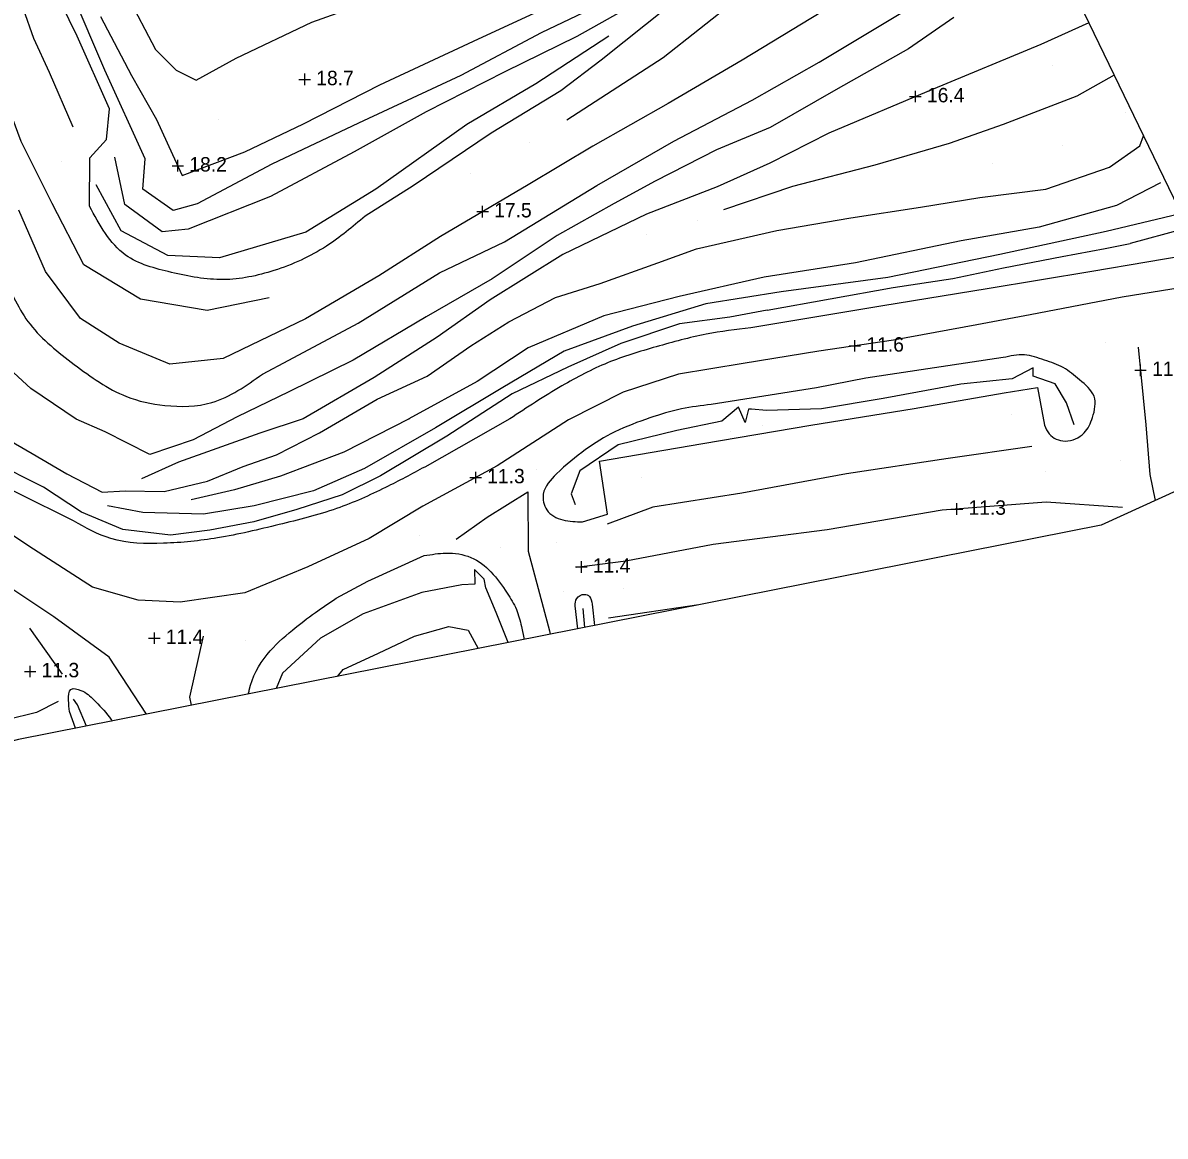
# Model space of a CAD drawing. Extents: x 2316231 to 2323598, y 363169 to 371906.
# Drawn here: x 2320484 to 2320880.2, y 369532.1 to 369918.1 of the extents above; entities that cross this region are included whole.
import ezdxf

# ---------------------------------------------------------------- set-up
doc = ezdxf.new("R2010")
doc.units = 0
for name, color, linetype in [('RD_DTM_BkLn1', 7, 'Continuous'), ('RD_DTM_Holes', 7, 'Continuous'), ('RD_DTM_Spot', 7, 'Continuous'), ('RD_DTM_TinHull', 7, 'Continuous'), ('RD_DTM_Void', 7, 'Continuous'), ('RD_EX_H2O', 7, 'Continuous'), ('RD_EX_Road', 7, 'Continuous')]:
    doc.layers.add(name, color=color, linetype=linetype)

msp = doc.modelspace()

# ---------------------------------------------------------------- linework, layer by layer
at = {"layer": 'RD_DTM_BkLn1'}
for p, q in [((2320678.249, 369715.097), (2320678.781, 369708.485)), ((2320718.471, 369716.35), (2320687.203, 369711.715)), ((2320497.804, 369692.273), (2320486.438, 369708.269))]:
    msp.add_line(p, q, dxfattribs=at)
for points in [[(2320890.624, 370119.716), (2320854.67, 370105.096), (2320824.737, 370091.718), (2320798.041, 370073.658), (2320761.256, 370054.377), (2320722.698, 370033.486), (2320697.589, 370022.782), (2320670.573, 370008.164), (2320638.057, 369990.65), (2320598.275, 369970.046), (2320568.854, 369953.416), (2320537.164, 369939.293), (2320520.212, 369927.706), (2320530.002, 369908.919), (2320537.229, 369901.735), (2320544.104, 369898.284), (2320558.001, 369905.94), (2320584.209, 369918.359), (2320607.024, 369926.567), (2320672.197, 369958.233), (2320716.019, 369979.773), (2320778.692, 370010.373), (2320825.216, 370034.958), (2320852.125, 370018.044)], [(2320879.005, 370020.78), (2320867.89, 370014.415), (2320857.257, 370007.846), (2320852.965, 369994.208), (2320826.144, 369975.823), (2320796.908, 369960.249), (2320762.152, 369944.511), (2320731.25, 369925.921), (2320706.051, 369906.01), (2320672.683, 369884.375)], [(2320846.121, 370003.875), (2320819.758, 369989.692), (2320786.161, 369974.117), (2320753.683, 369959.773), (2320725.332, 369945.903), (2320695.859, 369930.004), (2320663.758, 369914.691), (2320635.931, 369899.875), (2320600.474, 369883.297), (2320570.391, 369869.121), (2320544.447, 369855.352), (2320536.196, 369853.087), (2320525.687, 369860.434), (2320526.469, 369871.019), (2320512.487, 369901.765), (2320501.093, 369928.271), (2320493.497, 369945.114)], [(2320569.459, 369822.765), (2320547.933, 369818.395), (2320524.884, 369822.284), (2320505.191, 369834.205), (2320494.254, 369855.46), (2320483.409, 369876.949), (2320477.252, 369893.898), (2320466.119, 369909.363), (2320454.644, 369921.515), (2320476.509, 369937.799), (2320484.205, 369923.024), (2320487.742, 369912.811), (2320493.16, 369901.06), (2320501.409, 369882.112)], [(2320719.422, 369937.163), (2320697.207, 369925.152), (2320676.162, 369913.406), (2320651.158, 369901.105), (2320623.864, 369887.23), (2320598.965, 369873.389), (2320569.932, 369857.915), (2320541.38, 369846.609), (2320532.372, 369845.664), (2320519.389, 369855.192), (2320515.983, 369871.61)], [(2320761.155, 369921.965), (2320733.465, 369905.215), (2320707.874, 369890.151), (2320681.734, 369875.372), (2320659.231, 369861.923), (2320628.86, 369844.084), (2320607.503, 369830.462), (2320582.025, 369815.476), (2320553.529, 369801.787), (2320535.061, 369799.763), (2320517.402, 369807.066), (2320503.988, 369815.607), (2320491.892, 369831.92), (2320482.631, 369853.166)], [(2320806.943, 369919.979), (2320791.175, 369909.106), (2320766.76, 369895.42), (2320743.267, 369881.864), (2320724.614, 369874.141), (2320703.281, 369863.239), (2320689.113, 369855.517), (2320669.387, 369844.416), (2320646.753, 369829.417), (2320623.858, 369816.207), (2320598.638, 369801.198), (2320576.237, 369790.144), (2320558.388, 369781.496), (2320543.163, 369773.509), (2320528.041, 369768.512), (2320512.532, 369776.31), (2320502.503, 369780.676), (2320486.817, 369791.352), (2320474.931, 369802.246)], [(2320853.737, 369918.105), (2320837.036, 369910.626), (2320799.718, 369895.181), (2320763.548, 369879.832), (2320743.151, 369869.499), (2320724.799, 369861.314), (2320700.359, 369851.776), (2320671.278, 369837.865), (2320646.111, 369822.114), (2320627.68, 369809.174), (2320605.882, 369795.216), (2320581.205, 369780.846), (2320566.197, 369775.882), (2320538.033, 369765.834), (2320525.223, 369759.983)], [(2320687.269, 369913.532), (2320661.986, 369896.994), (2320638.064, 369882.89), (2320606.446, 369860.515), (2320582.215, 369845.501), (2320552.225, 369836.62), (2320534.288, 369837.482), (2320518.097, 369846.036), (2320509.495, 369861.951)], [(2320862.477, 369900.047), (2320849.618, 369892.725), (2320824.064, 369882.889), (2320805.349, 369876.347), (2320779.513, 369868.749), (2320750.969, 369861.378), (2320727.065, 369853.344)], [(2320461.89, 369783.469), (2320487.259, 369768.766), (2320499.343, 369761.794), (2320511.531, 369755.372), (2320519.537, 369755.806), (2320533.094, 369755.673), (2320548.04, 369759.198), (2320560.475, 369764.252), (2320572.006, 369768.322), (2320586.926, 369775.928), (2320606.891, 369787.646), (2320624.264, 369795.611), (2320639.423, 369806.127), (2320652.639, 369814.494), (2320668.755, 369822.903), (2320684.202, 369827.786), (2320704.291, 369834.94), (2320717.635, 369839.787), (2320745.533, 369846.105), (2320771.174, 369850.545), (2320795.305, 369854.228), (2320815.972, 369857.613), (2320838.828, 369860.447), (2320860.876, 369868.086), (2320871.433, 369875.499), (2320872.696, 369878.933)], [(2320878.622, 369862.672), (2320863.318, 369854.843), (2320836.538, 369847.295), (2320809.491, 369842.513), (2320772.852, 369834.956), (2320741.093, 369829.916), (2320711.676, 369823.258), (2320685.552, 369816.549), (2320659.329, 369805.457), (2320641.612, 369793.728), (2320617.942, 369780.803), (2320617.965, 369780.814), (2320595.414, 369769.221), (2320573.364, 369760.908), (2320557.456, 369756.151), (2320542.432, 369752.682)], [(2320886.875, 369854.365), (2320887.419, 369852.354), (2320859.79, 369845.8), (2320822.868, 369837.839), (2320784.046, 369829.81), (2320747.027, 369824.896), (2320720.871, 369820.74), (2320695.484, 369812.994), (2320671.745, 369804.329), (2320650.55, 369791.718), (2320627.167, 369777.678), (2320602.537, 369763.622), (2320584.839, 369755.805), (2320564.208, 369750.61), (2320546.635, 369747.749), (2320525.628, 369748.402), (2320513.364, 369750.676)], [(2320899.096, 369828.432), (2320865.244, 369823.009), (2320833.334, 369816.902), (2320814.869, 369813.372), (2320785.942, 369808.06), (2320760.046, 369804.318), (2320733.9, 369800.015), (2320711.478, 369796.268), (2320692.18, 369790.032), (2320673.259, 369780.434), (2320648.519, 369764.523), (2320622.809, 369750.54), (2320604.151, 369739.366), (2320582.823, 369729.464), (2320561.039, 369720.532), (2320538.574, 369717.201), (2320524.064, 369717.923), (2320508.146, 369722.418), (2320486.114, 369736.621), (2320466.942, 369749.551)], [(2320742.207, 369818.546), (2320729.212, 369816.124), (2320711.776, 369813.713), (2320691.464, 369806.932), (2320673, 369798.759), (2320653.709, 369789.465), (2320631.099, 369774.792), (2320608.044, 369761.043), (2320594.815, 369754.464), (2320579.064, 369749.414), (2320564.091, 369745.068), (2320548.89, 369742.174), (2320535.303, 369740.542), (2320518.686, 369742.444), (2320504.427, 369748.493), (2320491.204, 369757.123), (2320473.183, 369766.125)], [(2320870.882, 369805.693), (2320873.495, 369778.768), (2320874.929, 369761.517), (2320876.694, 369752.51)], [(2320848.662, 369778.765), (2320845.956, 369786.354), (2320842.031, 369792.961), (2320834.456, 369795.572), (2320834.402, 369798.472), (2320827.122, 369794.641), (2320809.385, 369792.838), (2320782.405, 369787.91), (2320761.017, 369784.326), (2320741.904, 369783.688), (2320736.769, 369784.185), (2320735.645, 369784.235), (2320734.487, 369779.564), (2320732.231, 369784.926), (2320726.407, 369780.031), (2320710.788, 369776.824), (2320690.54, 369771.773), (2320677.198, 369762.766), (2320674.17, 369754.81), (2320675.624, 369751.094)], [(2320526.896, 369678.387), (2320513.953, 369698.153), (2320494.831, 369712.151), (2320473.9, 369726.057), (2320453.263, 369740.557), (2320436.136, 369753.107), (2320412.476, 369763.057), (2320387.554, 369770.125), (2320361.478, 369773.264), (2320347.912, 369773.734)], [(2320833.989, 369771.203), (2320804.989, 369767.116), (2320769.71, 369761.767), (2320733.424, 369755.029), (2320702.543, 369750.244), (2320686.709, 369744.273)], [(2320634.265, 369739.13), (2320645.026, 369746.689), (2320659.121, 369755.479), (2320659.269, 369734.951), (2320666.7, 369707.34), (2320666.891, 369706.129)], [(2320865.442, 369750.13), (2320838.955, 369751.888), (2320802.868, 369749.174), (2320762.95, 369742.341), (2320723.412, 369737.305), (2320693.145, 369731.505), (2320676.058, 369729.249)], [(2320496.24, 369682.771), (2320488.769, 369678.962), (2320478.493, 369676.404), (2320476.678, 369691.645), (2320469.359, 369710.049), (2320458.349, 369727.582), (2320445.265, 369739.427)], [(2320652.309, 369703.239), (2320648.183, 369713.669), (2320644.548, 369722.185), (2320643.978, 369725.279), (2320640.644, 369728.589), (2320640.822, 369723.507), (2320636.246, 369723.304), (2320622.372, 369720.628), (2320602.091, 369713.195), (2320587.323, 369704.745), (2320574.101, 369692.657), (2320571.875, 369687.3)], [(2320593.209, 369691.528), (2320595.073, 369693.916), (2320607.387, 369699.545), (2320619.893, 369705.442), (2320631.747, 369708.836), (2320638.474, 369707.533), (2320641.995, 369701.195)], [(2320542.526, 369681.485), (2320541.978, 369684.258), (2320546.701, 369705.515)], [(2320506.167, 369674.28), (2320503.025, 369681.625), (2320501.641, 369683.666)]]:
    msp.add_lwpolyline(points, dxfattribs=at)
at = {"layer": 'RD_DTM_Holes'}
msp.add_lwpolyline([(2321124.606, 370283.08), (2321175.43, 370167.171), (2321165.892, 370142.913), (2321102.435, 370077.997), (2320995.795, 370021.474), (2320962.442, 369979.593), (2320898.768, 369979.08), (2320851.962, 369921.773), (2320884.841, 369853.84), (2320943.763, 369869.068), (2321020.605, 369919.215), (2321168.221, 369992.199), (2321311.04, 369921.856), (2321333.631, 369793.28), (2321191.287, 369743.45), (2321181.751, 369712.515), (2321194.283, 369686.43), (2321363.394, 369755.241)], dxfattribs=at)
at = {"layer": 'RD_DTM_Spot'}
for p, q in [((2320841.104, 369903.401), (2320841.104, 369903.401)), ((2320581.797, 369898.529), (2320581.797, 369898.529)), ((2320866.588, 369887.113), (2320866.588, 369887.113)), ((2320551.76, 369884.533), (2320551.76, 369884.533)), ((2320659.673, 369876.558), (2320659.673, 369876.558)), ((2320844.656, 369875.449), (2320844.656, 369875.449)), ((2320497.303, 369869.935), (2320497.303, 369869.935)), ((2320639.117, 369865.888), (2320639.117, 369865.888)), ((2320820.334, 369869.406), (2320820.334, 369869.406)), ((2320717.929, 369849.431), (2320717.929, 369849.431)), ((2320700.213, 369844.852), (2320700.213, 369844.852)), ((2320859.491, 369807.4), (2320859.491, 369807.4)), ((2320826.781, 369782.299), (2320826.781, 369782.299)), ((2320740.62, 369778.467), (2320740.62, 369778.467)), ((2320729.447, 369776.362), (2320729.447, 369776.362)), ((2320662.239, 369763.299), (2320662.239, 369763.299)), ((2320838.669, 369762.659), (2320838.669, 369762.659)), ((2320864.61, 369766.344), (2320864.61, 369766.344)), ((2320698.512, 369760.347), (2320698.512, 369760.347)), ((2320621.535, 369740.305), (2320621.535, 369740.305)), ((2320649.798, 369736.267), (2320649.798, 369736.267)), ((2320668.996, 369737.951), (2320668.996, 369737.951)), ((2320671.712, 369720.884), (2320671.712, 369720.884)), ((2320692.255, 369721.909), (2320692.255, 369721.909)), ((2320529.655, 369704.766), (2320529.655, 369704.766)), ((2320561.105, 369703.973), (2320561.105, 369703.973)), ((2320486.556, 369693.205), (2320486.556, 369693.205))]:
    msp.add_line(p, q, dxfattribs=at)
at = {"layer": 'RD_DTM_TinHull'}
msp.add_lwpolyline([(2321400.963, 368599.408), (2321534.916, 368777.939), (2321271.463, 369044.178), (2321175.279, 369261.496), (2321099.267, 369551.406), (2321096.219, 369852.637), (2320858.06, 369744.011), (2320482.587, 369669.607), (2320232.924, 369604.892), (2319951.333, 369602.051), (2320092.085, 369259.27), (2319866.523, 369058.699), (2319771.694, 369171.639), (2319557.442, 369523.873), (2318254.179, 368711.432)], dxfattribs=at)
at = {"layer": 'RD_DTM_Void'}
for p, q in [((2320579.797, 369898.529), (2320583.797, 369898.529)), ((2320581.797, 369896.529), (2320581.797, 369900.529)), ((2320793.587, 369890.579), (2320793.587, 369894.579)), ((2320791.587, 369892.579), (2320795.587, 369892.579)), ((2320537.771, 369866.586), (2320537.771, 369870.586)), ((2320535.771, 369868.586), (2320539.771, 369868.586)), ((2320643.493, 369850.679), (2320643.493, 369854.679)), ((2320641.493, 369852.679), (2320645.493, 369852.679)), ((2320770.585, 369806.13), (2320774.585, 369806.13)), ((2320772.585, 369804.13), (2320772.585, 369808.13)), ((2320871.66, 369795.677), (2320871.66, 369799.677)), ((2320869.66, 369797.677), (2320873.66, 369797.677)), ((2320641.08, 369758.477), (2320641.08, 369762.477)), ((2320639.08, 369760.477), (2320643.08, 369760.477)), ((2320807.99, 369747.559), (2320807.99, 369751.559)), ((2320805.99, 369749.559), (2320809.99, 369749.559)), ((2320677.742, 369727.472), (2320677.742, 369731.472)), ((2320675.742, 369729.472), (2320679.742, 369729.472)), ((2320527.655, 369704.766), (2320531.655, 369704.766)), ((2320529.655, 369702.766), (2320529.655, 369706.766)), ((2320486.556, 369691.205), (2320486.556, 369695.205)), ((2320484.556, 369693.205), (2320488.556, 369693.205))]:
    msp.add_line(p, q, dxfattribs=at)
at = {"layer": 'RD_EX_H2O'}
for points in [[(2320942.446, 369852.459), (2320923.822, 369850.683), (2320901.566, 369848.812), (2320886.019, 369846.493), (2320868.021, 369841.679)], [(2320742.207, 369818.546), (2320785.862, 369826.372), (2320806.584, 369829.487), (2320824.15, 369833.202), (2320844.538, 369837.128), (2320859.401, 369839.843), (2320868.021, 369841.679)]]:
    msp.add_lwpolyline(points, dxfattribs=at)
at = {"layer": 'RD_EX_Road'}
for p, q in [((2320824.066, 369802.052), (2320776.357, 369794.987)), ((2320652.925, 369780.802), (2320623.426, 369764.116)), ((2320676.502, 369708.033), (2320675.544, 369715.942)), ((2320681.438, 369716.554), (2320682.332, 369709.189)), ((2320656.973, 369708.815), (2320657.894, 369704.346)), ((2320502.313, 369673.516), (2320500.181, 369679.323))]:
    msp.add_line(p, q, dxfattribs=at)
for points in [[(2320567.105, 369796.337), (2320576.268, 369801.205), (2320600.386, 369813.982), (2320628.552, 369831.473), (2320651.132, 369842.245), (2320683.14, 369861.684), (2320709.778, 369877.068), (2320736.973, 369891.371), (2320760.171, 369904.501), (2320780.972, 369916.968), (2320800.68, 369928.912), (2320833.766, 369947.986), (2320858.279, 369963.381), (2320874.221, 369975.388), (2320892.051, 369982.519), (2320906.767, 369982.695), (2320925.078, 369982.494), (2320949.188, 369984.176), (2320964.962, 369996.308), (2320974.51, 370008.706), (2320986.355, 370021.913), (2320992.021, 370026.256)], [(2320841.864, 370009.258), (2320847.28, 370011.109), (2320851.506, 370008.615), (2320850.576, 370002.347), (2320840.724, 369994.47), (2320805.963, 369977.663), (2320766.893, 369960.136), (2320747.805, 369950.785), (2320730.157, 369939.506), (2320707.97, 369923.819), (2320684.632, 369905.147), (2320670.586, 369894.615), (2320646.458, 369879.926), (2320619.379, 369861.622), (2320602.713, 369851.068)], [(2320507.133, 369854.577), (2320507.259, 369871.371), (2320513.034, 369877.728), (2320514.041, 369888.346), (2320502.899, 369913.48), (2320489.286, 369941.447)], [(2320510.969, 369920.287), (2320521.673, 369899.865), (2320530.401, 369884.58), (2320535.952, 369872.468), (2320539.335, 369865.246), (2320561.003, 369873.381), (2320581.352, 369883.086), (2320607.879, 369896.616), (2320640.362, 369911.825), (2320673.599, 369927.313)], [(2321040.54, 369861.944), (2321015.372, 369857.615), (2320984.804, 369852.524), (2320950.199, 369847.082), (2320916.155, 369841.334), (2320892.905, 369838.344), (2320854.731, 369831.941), (2320818.448, 369825.866), (2320782.324, 369820.061), (2320736.523, 369812.379)], [(2320776.357, 369794.987), (2320759.276, 369791.563), (2320722.792, 369785.781)], [(2320678.181, 369745.112), (2320686.771, 369747.746), (2320684.083, 369766.094), (2320719.917, 369772.294), (2320757.37, 369778.622), (2320793.18, 369784.44), (2320824.367, 369789.899), (2320835.91, 369791.675), (2320838.308, 369778.579)], [(2320501.602, 369745.427), (2320482.504, 369754.928), (2320452.058, 369770.263), (2320414.016, 369788.613)], [(2320592.719, 369718.602), (2320603.652, 369724.485), (2320623.266, 369733.383)]]:
    msp.add_lwpolyline(points, dxfattribs=at)
for points in [[(2320406.871, 369864.055), (2320414.163, 369872.507), (2320428.035, 369879.477), (2320437.981, 369881.239), (2320448.49, 369878.636), (2320456.929, 369873.222), (2320465.381, 369863.547), (2320473.612, 369847.893), (2320478.003, 369830.74), (2320486.531, 369813.623), (2320501.876, 369799.699), (2320519.932, 369788.595), (2320533.261, 369785.473), (2320549.577, 369786.473), (2320567.105, 369796.337)], [(2320602.713, 369851.068), (2320589.308, 369840.701), (2320571.101, 369832.245), (2320553.56, 369829.115), (2320535.552, 369831.619), (2320519.697, 369837.62), (2320507.133, 369854.577)], [(2320736.523, 369812.379), (2320721.033, 369810.161), (2320703.712, 369805.816), (2320686.856, 369800.243), (2320670.99, 369792.248), (2320652.925, 369780.802)], [(2320838.308, 369778.579), (2320839.969, 369775.58), (2320845.51, 369773.125), (2320852.089, 369775.949), (2320855.004, 369781.331), (2320855.522, 369788.635), (2320850.547, 369794.314), (2320844.88, 369798.613), (2320838.339, 369801.185), (2320831.367, 369803.006), (2320824.066, 369802.052)], [(2320722.792, 369785.781), (2320712.465, 369784.257), (2320701.479, 369781.129), (2320689.337, 369776.298), (2320679.19, 369770.153), (2320669.133, 369761.748), (2320664.535, 369754.722), (2320665.745, 369749.253), (2320671.293, 369745.775), (2320678.181, 369745.112)], [(2320623.426, 369764.116), (2320609.857, 369757.033), (2320592.847, 369749.718), (2320572.878, 369744.149), (2320551.598, 369739.542), (2320532.872, 369737.665), (2320514.59, 369739.327), (2320501.602, 369745.427)], [(2320623.266, 369733.383), (2320630.791, 369734.269), (2320639.428, 369732.754), (2320646.385, 369727.752), (2320651.992, 369720.418), (2320655.203, 369714.748), (2320656.973, 369708.815)], [(2320675.544, 369715.942), (2320676.141, 369718.536), (2320678.801, 369719.951), (2320680.517, 369719.223), (2320681.438, 369716.554)], [(2320562.267, 369685.397), (2320562.55, 369686.755), (2320568.793, 369699.158), (2320577.546, 369707.547), (2320585.489, 369713.669), (2320592.719, 369718.602)], [(2320500.181, 369679.323), (2320499.896, 369683.259), (2320500.735, 369687.009), (2320504.207, 369686.678), (2320508.654, 369683.363), (2320514.054, 369677.367), (2320514.951, 369676.02)]]:
    msp.add_spline(points, degree=3, dxfattribs=at)

# ---------------------------------------------------------------- texts
at = {"layer": 'RD_DTM_Void'}
for s, p in [('18.7', (2320585.797, 369896.529)), ('16.4', (2320797.587, 369890.579)), ('18.2', (2320541.771, 369866.586)), ('17.5', (2320647.493, 369850.679)), ('11.6', (2320776.585, 369804.13)), ('11.7', (2320875.66, 369795.677)), ('11.3', (2320645.08, 369758.477)), ('11.3', (2320811.99, 369747.559)), ('11.4', (2320681.742, 369727.472)), ('11.4', (2320533.655, 369702.766)), ('11.3', (2320490.556, 369691.205))]:
    msp.add_text(s, height=5, dxfattribs=at).set_placement(p)

doc.saveas('drawing.dxf')
